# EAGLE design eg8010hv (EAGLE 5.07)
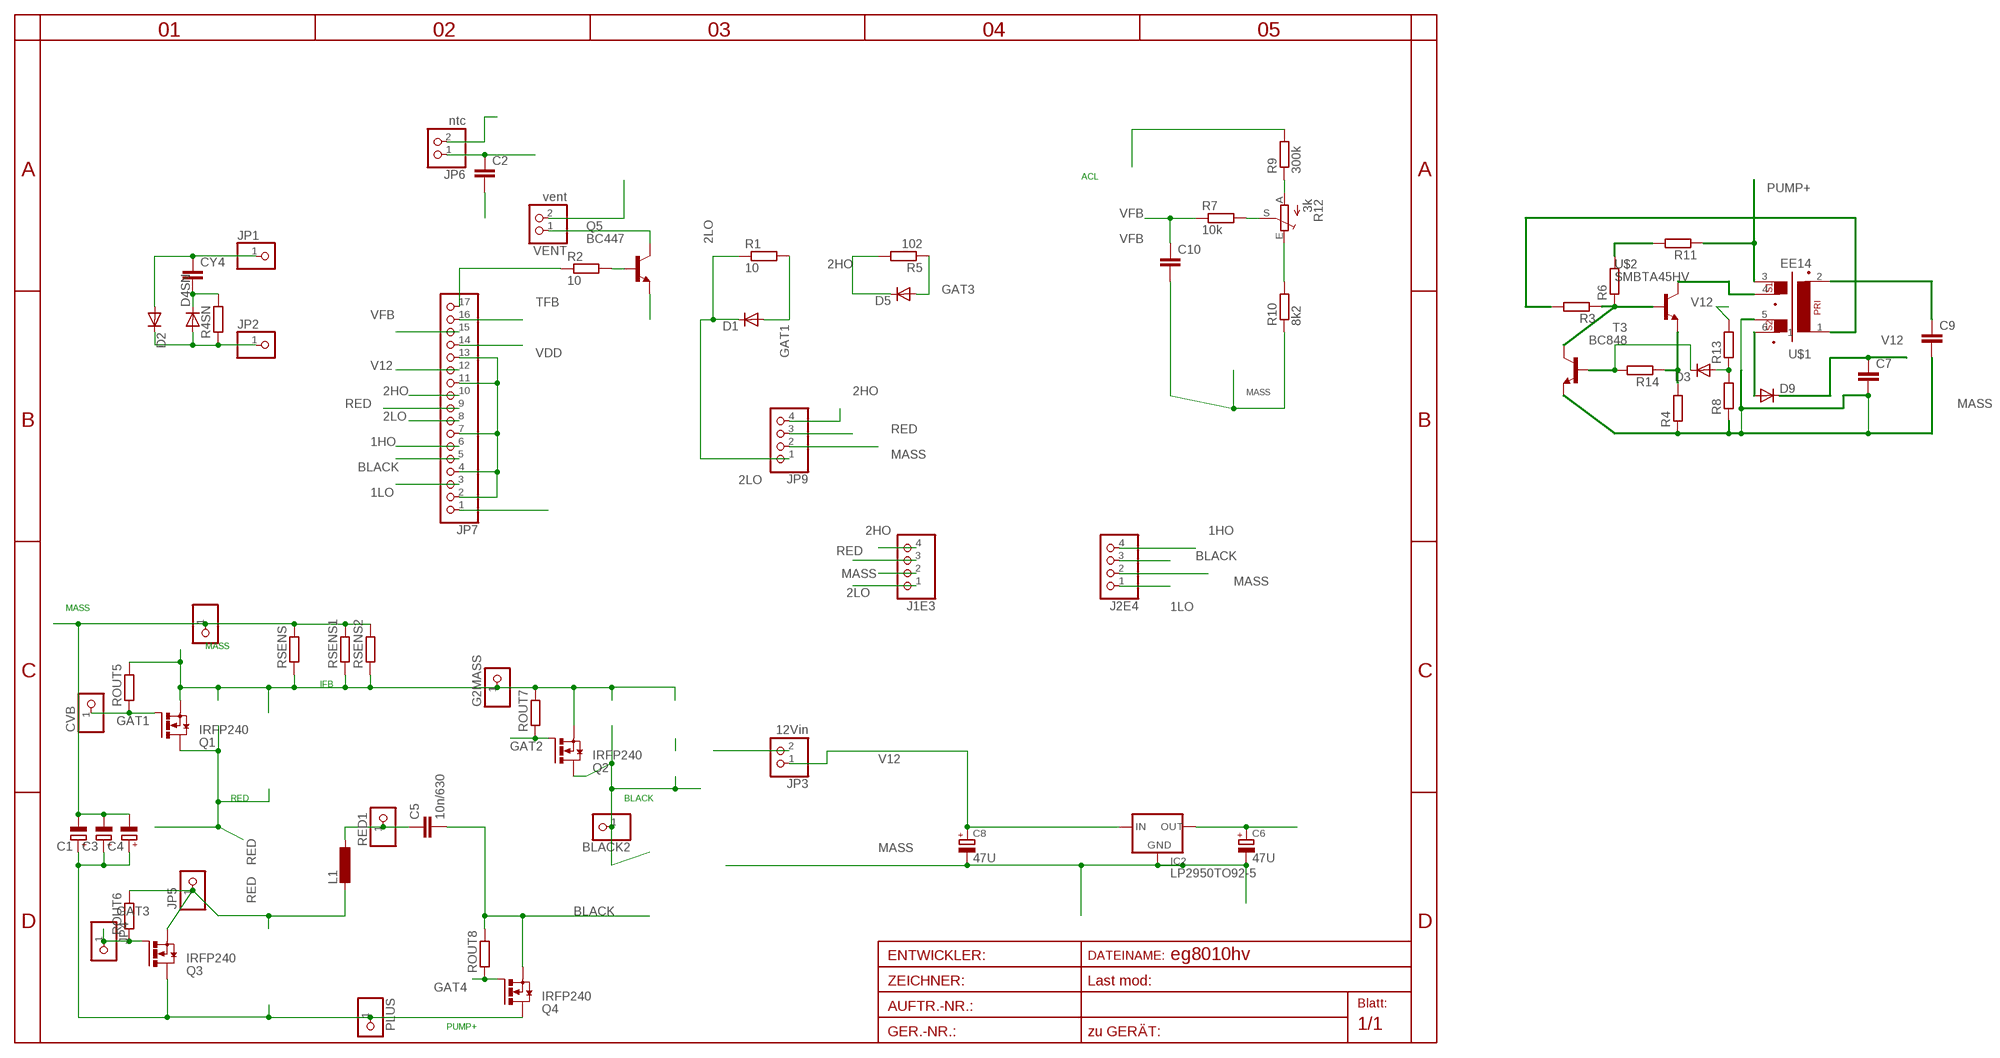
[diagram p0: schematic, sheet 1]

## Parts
BLACK2  PINHD-1X12MM3  [1X2MM3]
C1  CPOL-EUE5-13  [E5-13]
C2  C-EUC1206  [C1206]
C3  CPOL-EUE5-13  [E5-13]
C4  CPOL-EUE5-13  [E5-13]
C5  10n/630  C-EU275-173X316  [C275-173X316]
C6  47U  CPOL-EUE2.5-6  [E2,5-6]
C7  C-EUC1206  [C1206]
C8  47U  CPOL-EUE2.5-6  [E2,5-6]
C9  C-EUC0805  [C0805]
C10  C-EUC0805  [C0805]
CVB  PINHD-1X11MM0  [1X1MM0]
CY4  CXXC10B5  [XC10B5]
D1  DIODE-MINIMELF  [MINIMELF]
D2  DIODE-SMC  [SMC]
D3  DIODE-MINIMELF  [MINIMELF]
D4SN  DIODE-P1-10  [P1-10]
D5  DIODE-MINIMELF  [MINIMELF]
D9  DIODE-SMA-DO214  [SMA-DO214AC]
G2MASS  PINHD-1X11MM0  [1X1MM0]
IC2  LP2950TO92-5  [T092-5]
J1E3  PINHD-1X4  [1X04]
J2E4  PINHD-1X4  [1X04]
JP1  PINHD-1X11MM0  [1X1MM0]
JP2  PINHD-1X11MM0  [1X1MM0]
JP3  12Vin  PINHD-1X2STR  [1X02]
JP4  PINHD-1X11MM0  [1X1MM0]
JP5  PINHD-1X11MM0  [1X1MM0]
JP6  ntc  PINHD-1X2STR  [1X02]
JP7  PINHD-1X17  [1X17]
JP9  PINHD-1X4  [1X04]
L1  L-EU4.13  [0204/13]
MINUS  PINHD-1X12MM3  [1X2MM3]
PLUS  PINHD-1X12MM3  [1X2MM3]
Q1  IRFP240  [TO247BV]
Q2  IRFP240  [TO247BV]
Q3  IRFP240  [TO247BV]
Q4  IRFP240  [TO247BV]
Q5  BC447  [TO92-EBC]
R1  10  R-EU_R0805  [R0805]
R2  10  R-EU_R0805  [R0805]
R3  R-EU_R0805  [R0805]
R4  R-EU_R0805  [R0805]
R4SN  R-EU_0207/10  [0207/10]
R5  102  R-EU_R1206  [R1206]
R6  R-EU_R1206  [R1206]
R7  10k  R-EU_R0805  [R0805]
R8  R-EU_R0805  [R0805]
R9  300k  R-EU_0207/20  [0207/20]
R10  8k2  R-EU_R0805  [R0805]
R11  R-EU_R1206  [R1206]
R12  3k  TRIM_EU-CA6V  [CA6V]
R13  R-EU_R0805  [R0805]
R14  R-EU_R0805  [R0805]
RED1  PINHD-1X12MM3  [1X2MM3]
ROUT5  R-EU_0207/10  [0207/10]
ROUT6  R-EU_0207/10  [0207/10]
ROUT7  R-EU_0207/10  [0207/10]
ROUT8  R-EU_0207/10  [0207/10]
RSENS  R-EU_0204/7  [0204/7]
RSENS1  R-EU_0204/7  [0204/7]
RSENS2  R-EU_0204/7  [0204/7]
T3  BC848  [SOT23]
U$1  EE14  [EE14]
U$2  SMBTA45HV  [SOT23HV]
VENT  vent  PINHD-1X2STR  [1X02]

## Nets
1HO: J2E4.4 JP7.6
1LO: J2E4.1 JP7.3
2HO: D5.C J1E3.4 JP7.10 JP9.4 R5.2
2LO: D1.C J1E3.1 JP7.8 JP9.1 R1.1
A: D9.A U$1.6
ACL: C5.1 L1.1 R9.2 RED1.1
B1C2: R3.1 R6.1 T3.C U$2.1(B)
BLACK: BLACK2.1 C5.2 J2E4.3 JP7.5 Q2.D Q4.S ROUT8.2
C1: U$1.4 U$2.3(C)
DRAIN: D2.C D4SN.A JP2.1 R4SN.1
EB: R4.2 R14.1 U$2.2(E)
GAT1: CVB.1 D1.A Q1.G R1.2 ROUT5.1
GAT2: Q2.G ROUT7.1
GAT3: D5.A JP4.1 Q3.G R5.1 ROUT6.1
GAT4: Q4.G ROUT8.1
IFB: G2MASS.1 JP7.1 Q1.S Q2.S ROUT5.2 ROUT7.2 RSENS1.1 RSENS2.1 RSENS.1
MASS: C1.- C2.2 C3.- C4.- C6.- C7.2 C8.- C9.2 C10.2 IC2.2(GND) J1E3.2 J2E4.2 JP3.2 JP7.2 JP7.4 JP7.7 JP7.11 JP7.13 JP9.2 MINUS.1 Q5.E R4.1 R8.1 R10.1 RSENS1.2 RSENS2.2 RSENS.2 T3.E U$1.5
N$1: Q5.C VENT.1
N$2: Q5.B R2.2
N$3: JP7.17 R2.1
N$6: R3.2 U$1.1
N$7: C9.1 U$1.2
N$8: R6.2 R11.2
N$9: D3.C R14.2 T3.B
N$10: D3.A R8.2 R13.1
N$29: R10.2 R12.E
N$30: R9.1 R12.A
N$31: R7.2 R12.S
PUMP+: C1.+ C3.+ C4.+ PLUS.1 Q3.D Q4.D R11.1 U$1.3
RED: J1E3.3 JP5.1 JP7.9 JP9.3 L1.2 Q1.D Q3.S ROUT6.2
SNUB2: CY4.2 D4SN.C R4SN.2
SOURCE: CY4.1 D2.A JP1.1
TFB: C2.1 JP6.1 JP7.16
V12: C7.1 C8.+ D9.K(C) IC2.3(IN) JP3.1 JP7.12 R13.2
VDD: C6.+ IC2.1(OUT) JP6.2 JP7.14 VENT.2
VFB: C10.1 JP7.15 R7.1

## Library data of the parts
BLACK2 CVB G2MASS JP1 JP2 JP4 JP5 MINUS PLUS RED1 = pinhead:PINHD-1X1: PIN HEADER
C1 C3 C4 = rcl:CPOL-EU: POLARIZED CAPACITOR, European symbol
C2 C5 C7 C9 C10 = rcl:C-EU: CAPACITOR, European symbol
C6 C8 = rcl-2:CPOL-EU: POLARIZED CAPACITOR, European symbol
CY4 = rcl:CX: X CAPACITOR
D1-D3 D4SN D5 D9 = diode:DIODE-: DIODE
IC2 = v-reg:LP2950?*: Source: http://cache.national.com/ds/LP/LP2950.pdf
J1E3 J2E4 JP9 = pinhead:PINHD-1X4: PIN HEADER
JP3 JP6 VENT = pinhead:PINHD-1X2: PIN HEADER
JP7 = pinhead:PINHD-1X17: PIN HEADER
L1 = rcl:L-EU: INDUCTOR, European symbol
Q1-Q4 = transistor-power:IRFP240: HEXFET Power MosFet Source: http://www.irf.com/
Q5 = transistor-npn:BC447*: NPN Transistor
R1-R4 R4SN R5 R6 R8 R11 R13 R14 ROUT5-ROUT8 RSENS RSENS1 RSENS2 = rcl:R-EU_: RESISTOR, European symbol
R7 R9 R10 = rcl-2:R-EU_: RESISTOR, European symbol
R12 = pot:TRIM_EU-: POTENTIOMETER
T3 = transistor:BC848: NPN TRANSISTOR
U$1 = trafo:EE14
U$2 = transistor-npn:SMBTA45

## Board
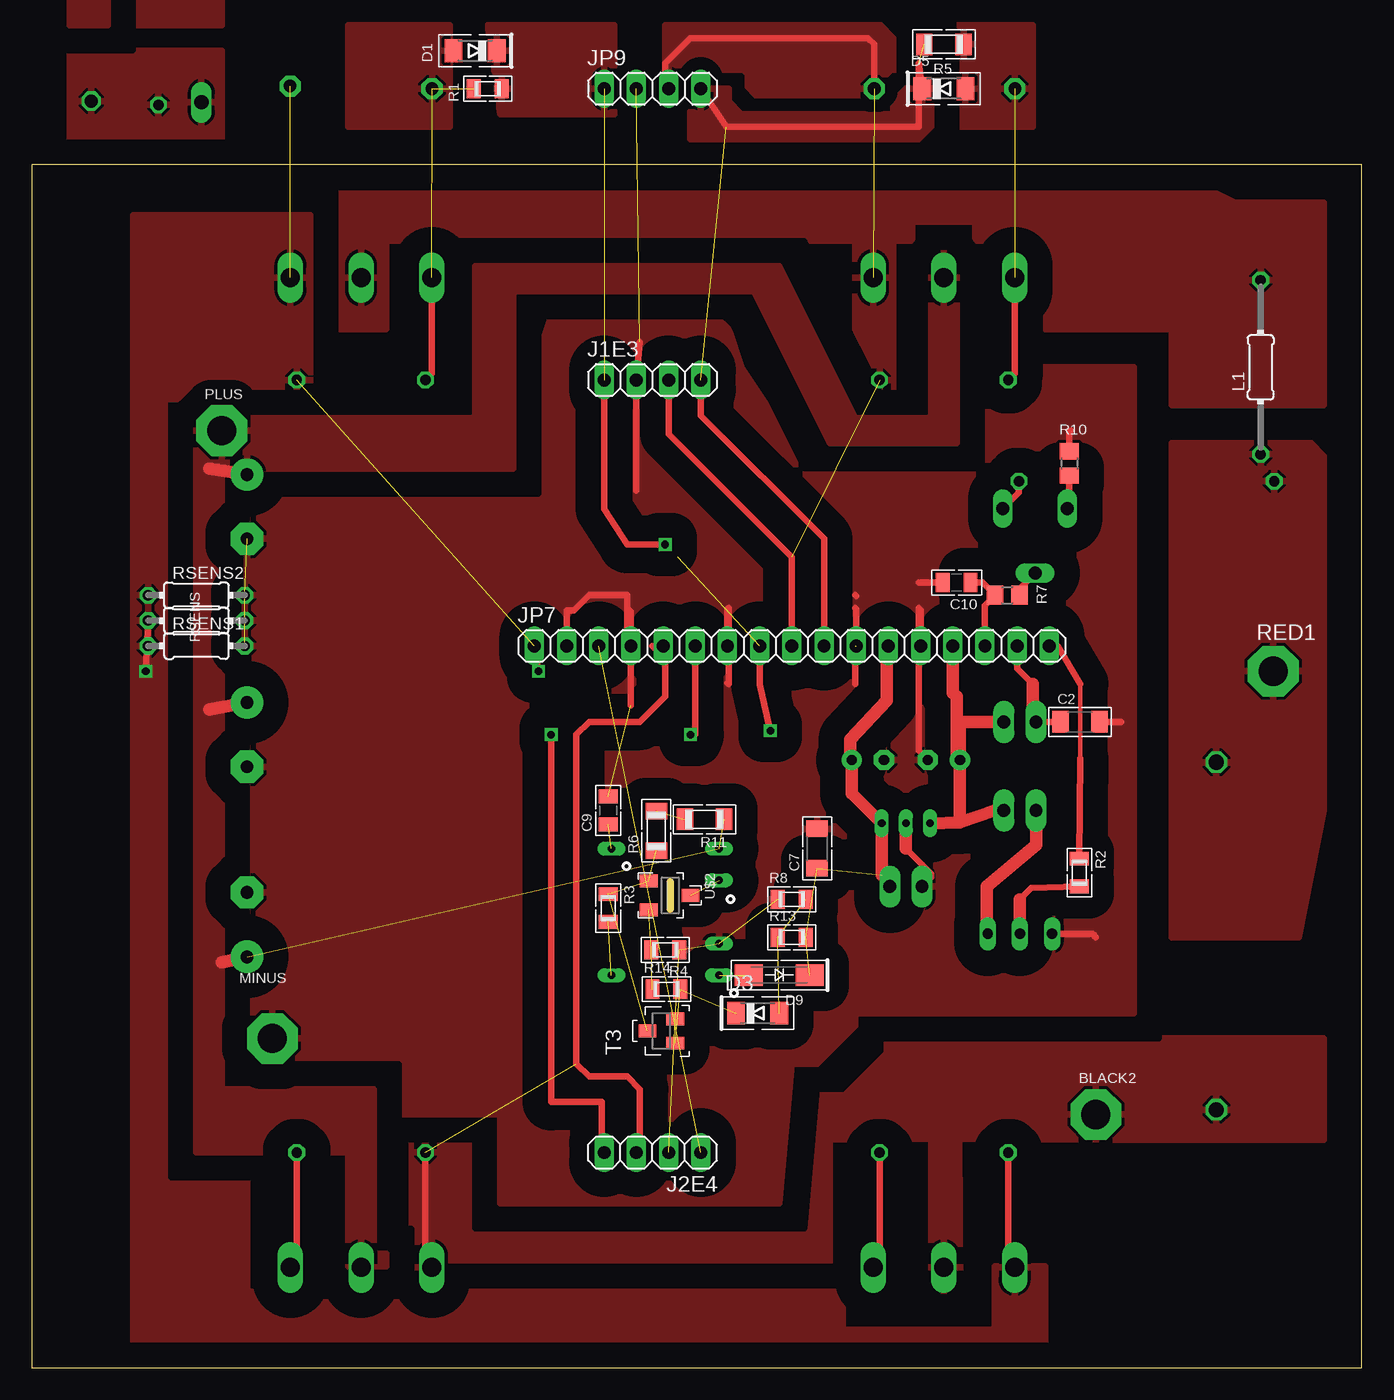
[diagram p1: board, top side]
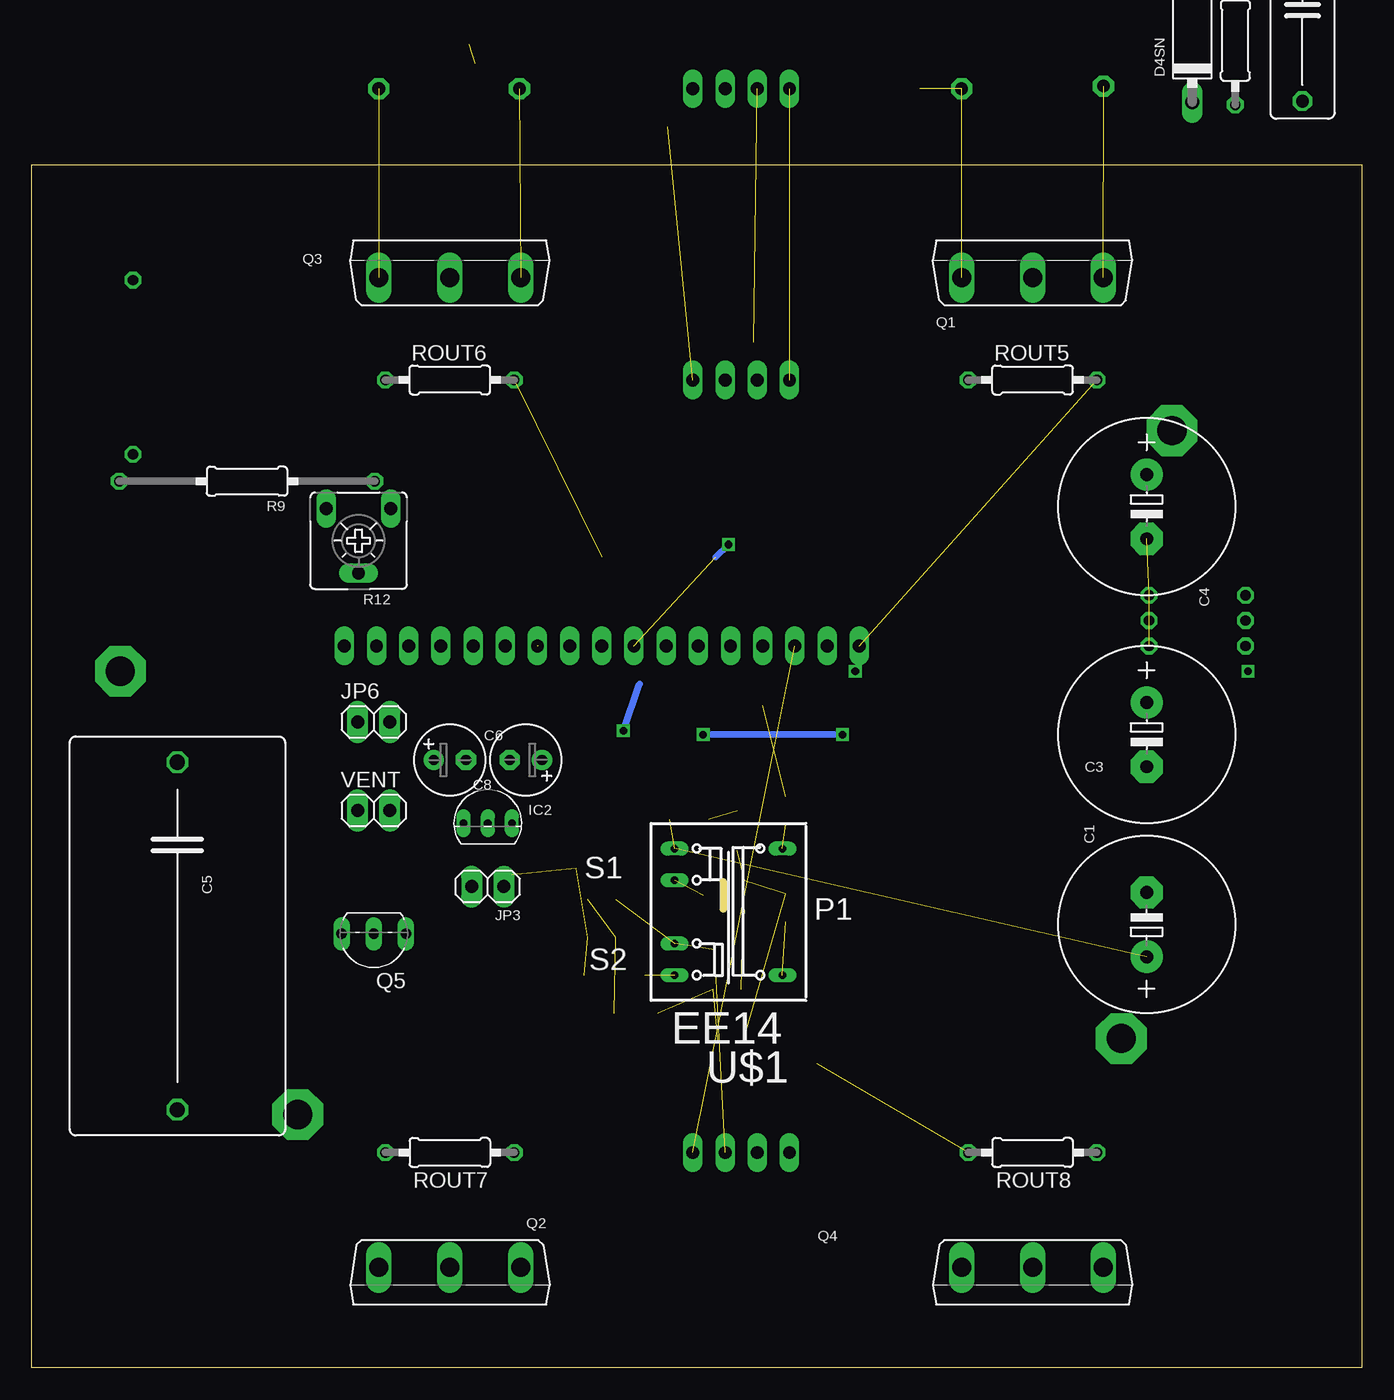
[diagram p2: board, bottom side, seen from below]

Size 105 x 95 mm. Coordinates in mm from the lower left corner, seen from the top.
Outline: 0,0 105,0 105,95 0,95 0,0
Copper layers (1*16): Top 0.035mm / dielectric 1.5mm / Bottom 0.035mm
Design rules "default *": minimum track width 10mil, minimum drill 20mil, track to track 8mil, track to pad 8mil, pad to pad 8mil, via to via 8mil, smd to smd 8mil, copper to edge 40mil, drill to drill 8mil, minimum pad ring 10mil, minimum via ring 8mil, stop-mask expansion 4mil, vias tented up to drill 0mil, thermal gap 10mil

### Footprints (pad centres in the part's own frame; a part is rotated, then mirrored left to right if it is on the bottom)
1X2MM3 = drill 2.3 pad 4 octagon: 1 0,0
E5-13 = drill 1.016 pad 2.54 round: + -2.54,0 | drill 1.016 pad 2.54 octagon: - 2.54,0
C1206 = smd 1.3 x 1.7: 1 -1.55,0; 2 1.55,0
C275-173X316 = drill 1.194 octagon: 1 -13.716,0; 2 13.716,0
E2,5-6 = drill 0.813 pad 1.6 round: + -1.27,0 | drill 0.813 pad 1.6 octagon: - 1.27,0
C0805 = smd 1.1 x 1.5: 1 -1.1,0; 2 1.1,0
1X1MM0 = drill 1 pad 1.676 octagon: 1 0,0
XC10B5 = drill 1.016 octagon: 1 -5.08,0; 2 5.08,0
MINIMELF = smd 1.4 x 1.8: A 1.7,0; C -1.7,0
SMC = smd 2.8 x 3.8: A 3.7,0; C -3.7,0
P1-10 = drill 1.118 long: A 5.08,0; C -5.08,0
SMA-DO214AC = smd 2.2 x 1.7: A 2.4,0; K -2.4,0
T092-5 = drill 0.6 pad 0.813 long: 1 -1.905,0; 2 0,0; 3 1.905,0
1X04 = drill 1.016 long: 1 -3.81,0; 2 -1.27,0; 3 1.27,0; 4 3.81,0
1X02 = drill 1.016 pad 1.676 long: 1 -1.27,0; 2 1.27,0
1X17 = drill 1.016 long: 1 -20.32,0; 2 -17.78,0; 3 -15.24,0; 4 -12.7,0; 5 -10.16,0; 6 -7.62,0; 7 -5.08,0; 8 -2.54,0; 9 0,0; 10 2.54,0; 11 5.08,0; 12 7.62,0; 13 10.16,0; 14 12.7,0; 15 15.24,0; 16 17.78,0; 17 20.32,0
0204/13 = drill 0.813 octagon: 1 -6.872,0; 2 6.872,0
TO247BV = drill 1.499 long: D 0,-2.921; G -5.588,-2.921; S 5.588,-2.921
TO92-EBC = drill 0.813 long: B 0,-1.27; C -2.54,-1.27; E 2.54,-1.27
R0805 = smd 1.1 x 1.5: 1 -1.1,0; 2 1.1,0
0207/10 = drill 0.813 octagon: 1 -5.08,0; 2 5.08,0
R1206 = smd 1.3 x 1.7: 1 -1.55,0; 2 1.55,0
R0805' = smd 1.3 x 1.5: 1 -0.95,0; 2 0.95,0
0207/20 = drill 0.813 octagon: 1 -10.08,0; 2 10.08,0
CA6V = drill 1.016 long: A -2.54,-2.54; E 2.54,-2.54; S 0,2.54
0204/7 = drill 0.813 octagon: 1 -3.81,0; 2 3.81,0
SOT23 = smd 1 x 1.4: B -0.95,-1.1; C 0,1.1; E 0.95,-1.1
EE14 = drill 0.6 pad 1 long: 1 4.25,-5; 2 4.25,5; 3 -4.25,5 | drill 0.6 pad 1.016 long: 4 -4.25,2.5; 5 -4.25,-2.5; 6 -4.25,-5
SOT23HV = smd 1 x 1.4: 1 -1.15,-1.7; 2 1.15,-1.7; 3 0,1.6

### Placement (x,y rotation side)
BLACK2  84,20 0 top
C1  17,35 90 bottom
C2  82.75,51 0 top
C3  17,50 270 bottom
C4  17,68 270 bottom
C5  93.5,34.1 270 bottom
C6  72,48 0 bottom
C7  62,41 90 top
C8  66,48 180 bottom
C9  45.5,44 90 top
C10  73,62 180 top
CVB  not placed on the board
CY4  not placed on the board
D1  not placed on the board
D2  not placed on the board
D3  57.3,28 0 top
D4SN  not placed on the board
D5  72,101 0 top  (outside the outline)
D9  59,31 180 top
G2MASS  not placed on the board
IC2  69,43 0 bottom
J1E3  49,78 0 top
J2E4  49,17 180 top
JP1  not placed on the board
JP2  not placed on the board
JP3  69,38 180 bottom
JP4  not placed on the board
JP5  66.5,101 180 top  (outside the outline)
JP6  78,51 0 bottom
JP7  60,57 0 top
JP9  49,101 0 top  (outside the outline)
L1  97,79 90 top
MINUS  19,26 0 top
PLUS  15,74 0 top
Q1  26,89 0 bottom
Q2  72,5 180 bottom
Q3  72,89 0 bottom
Q4  26,5 180 bottom
Q5  78,33 180 bottom
R1  not placed on the board
R2  82.7,39.1 270 top
R3  45.5,36.3 270 top
R4  50,33 180 top
R4SN  not placed on the board
R5  not placed on the board
R6  49.3,42.4 90 top
R7  10k  [R0805']  77,61 0 top
R8  60,37 0 top
R9  88,70 180 bottom
R10  8k2  [R0805']  81.9,71.4 270 top
R11  53.1,43.3 180 top
R12  79.2,65.3 180 bottom
R13  60,34 0 top
R14  50.1,29.9 0 top
RED1  98,55 0 top
ROUT5  26,78 0 bottom
ROUT6  72,78 0 bottom
ROUT7  72,17 180 bottom
ROUT8  26,17 180 bottom
RSENS  13,59 0 top
RSENS1  13,57 0 top
RSENS2  13,61 0 top
T3  49.7,26.6 90 top
U$1  50,36 0 bottom
U$2  50.4,37.3 270 top
VENT  78,44 0 bottom

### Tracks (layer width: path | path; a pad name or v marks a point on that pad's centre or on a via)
1HO  (via drill 0.6)
  Top 0.5: J2E4.4 45,17 45,21 41,21 v41,50 | v52,50 52.38,50 JP7.6
  Bottom 0.5: v41,50 v52,50
1LO  (1 unrouted)
2HO  (2 unrouted)
  Top 0.5: D5.C 70,103 70,98 54.81,98 JP9.4 | JP7.10 62.54,65.46 52.81,75.19 J1E3.4
  pour Top (isolate 1): 52,101 52,97 70,97 71,98 71,101 69,101 68,100 68,99 56,99 55,100 55,101
2LO  (via drill 0.6)  (2 unrouted)
  Top 0.5: J1E3.1 45.19,67.81 47,65 v50,65 | JP7.8 57.46,53.94 v58.3,50.3
  Bottom 0.5: v50,65 51,64 | v58.3,50.3 57.1,53.9 57,54
  pour Top (isolate 1): 36,106 46,106 46,99 37,99
A  (1 unrouted)
ACL
  pour Top (isolate 1): 90,73 101,73 102,72 102,44 100,34 90,34
B1C2  (3 unrouted)
BLACK  (1 unrouted)
  Top 0.5: ROUT8.2 31.08,8.43 Q4.S | J2E4.3 48,17 48,22 47,23 44,23 43,24 43,50 44,51 48,51 50,53 50,56 49,57 JP7.5
  pour Top (isolate 2, rank 4): 30,18 35,18 35,11 61,11 61,22 65,26 102,26 102,18 85,18 73.2,18.1 73.3,6.1 71,6.1 71,18.1 63,18 63,8 30,7
C1  (1 unrouted)
DRAIN
  pour Top (isolate 2, rank 2): 8,120 8,106 15,106 15,120
EB  (2 unrouted)
GAT1  (2 unrouted)
  Top 0.5: Q1.G 31.59,78.51 ROUT5.1
  pour Top (isolate 2): 25,98 25,106 33,106 33,98
GAT2
  Top 0.5: ROUT7.1 66.92,8.43 Q2.G
GAT3  (1 unrouted)
  Top 0.5: Q3.G 77.59,78.51 ROUT6.1
  pour Top (isolate 2, rank 2): 73,106 79,106 79,98 73,98
GAT4
  Top 0.5: ROUT8.1 20.92,8.43 Q4.G
IFB  (via drill 0.6)  (2 unrouted)
  Top 0.5: JP7.1 v40,55 | v9,55 RSENS.1 | ROUT7.2 77.08,8.92 78,8 78,7.51 | 78,7.51 78,7 | Q2.S 78,7.51
  pour Top (isolate 2, rank 3): 22,91 8,91 8,2 12,0 80,0 80,8 76,8 76,3 64,3 64,6 17,6 17,17 11,17 11,69 22,69
MASS  (10 unrouted)
  Top 0.5: 47.73,69.27 J1E3.2 48,81 | JP7.4 47.3,52.3 | 55,54 54.92,54.08 55,54.16 55,60 54.92,59.92 JP7.7 | JP7.4 47.3,59.7 47,60 | JP7.2 42.22,59.78 42.78,59.78 44,61 47,61 47,57.3 JP7.4 | 65.08,60.92 65,61 | 69,41 71,39 71,38.73 JP3.2 | R10.1 81.9,73.9 82,74 | Q5.E 83.73,34.27 84,34 | JP7.13 70.16,59.84 70,60 70,48.73 C6.- | JP7.11 65.08,59.92 65,60 | C2.2 86,51 | 70,62 C10.2 | 65,54 65,57
  Top 1: 69,41 IC2.2
  pour Top (isolate 2, rank 3): 16,20 16,70 39,71 39,77 41,83 54,83 55,82 56,79 60,73 73,73 73,79 87,79 87,28 65,28 65,27 62,24 60,24 59,13 37,13 37,20
N$1
  Top 0.5: Q5.C 75.4,34.81
  Top 1: VENT.1 79.27,41.27 75.4,38 75.4,34.81
N$2
  Top 0.5: R2.2 78.9,37.9 78,37
  Top 1: Q5.B 78,37
N$3
  Top 0.35: 82.75,48.1 82.75,54
  Top 0.5: JP7.17 81,57 82.75,54 | R2.1 82.75,48.1
N$6  (1 unrouted)
N$7  (1 unrouted)
N$8  (1 unrouted)
N$9  (2 unrouted)
N$10  (2 unrouted)
N$29
  Top 0.5: R10.2 81.9,68 R12.E
N$30
  Top 0.5: R9.1 77.92,69.1 R12.A
N$31
  Top 0.5: R7.2 77.95,61.51 R12.S
PUMP+  (2 unrouted)
  Top 1: 15,32 C1.+ | 14,52 C3.+ | 14,71 C4.+
  pour Top (isolate 2): 13,75 35,75 35,87 59,87 65,75 71,75 71,88 73,88 73,73 63,73 57,85 38,85 38,71 15,71 15,22 27,22 27,9 28,9 28,8 25,8 25,17 13,17
RED  (2 unrouted)
  Top 0.5: JP5.1 66.5,104.5 66,105 52,105 50,103 50,101.27 JP9.3 | JP7.9 60,64 50.27,73.73 J1E3.3
  pour Top (isolate 2, rank 4): 28,82 24,82 24,93 93,93 95,92 102,92 102,76 90,76 90,82 80,82 80,89 68,89 68,77 65,77 65,89 28,89
  pour Top (isolate 1, rank 2): 50,102 50,105 50,106 67,106 68,105 68,101 67,100 57,100 54,103 53,103 52,102 52,101
SNUB2
  pour Top (isolate 2, rank 2): 3,104 15,104 15,97 3,97
SOURCE
  pour Top (isolate 2): 3,120 6,120 6,106 3,106
TFB
  Top 0.5: JP7.16 77.78,55.22 79,54 | 79,51.27 JP6.1 C2.1
  Top 1: 79,51.27 79,54
V12  (3 unrouted)
  Top 0.5: C8.+ 64.62,48.11 | 67.09,38.91 68,38 JP3.1 | 67.5,56.32 JP7.12
  Top 1: C8.+ 64.73,45.37 IC2.3 67.09,38.91 | 64.62,48.11 64.62,49.62 67.5,52.7 67.5,56.32
VDD
  Top 0.5: C6.+ 73,48.27 | 73,53 72.7,53.3
  Top 1: 73,48.27 73,53 | IC2.1 73.25,43.05 | 73.25,43.05 73.27,44.47 C6.+ 73.27,51 JP6.2 | VENT.2 76,44 73.25,43.05 | 72.7,53.3 JP7.14
VFB
  Top 0.5: C10.1 75.05,62 R7.1 75.24,60.19 JP7.15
